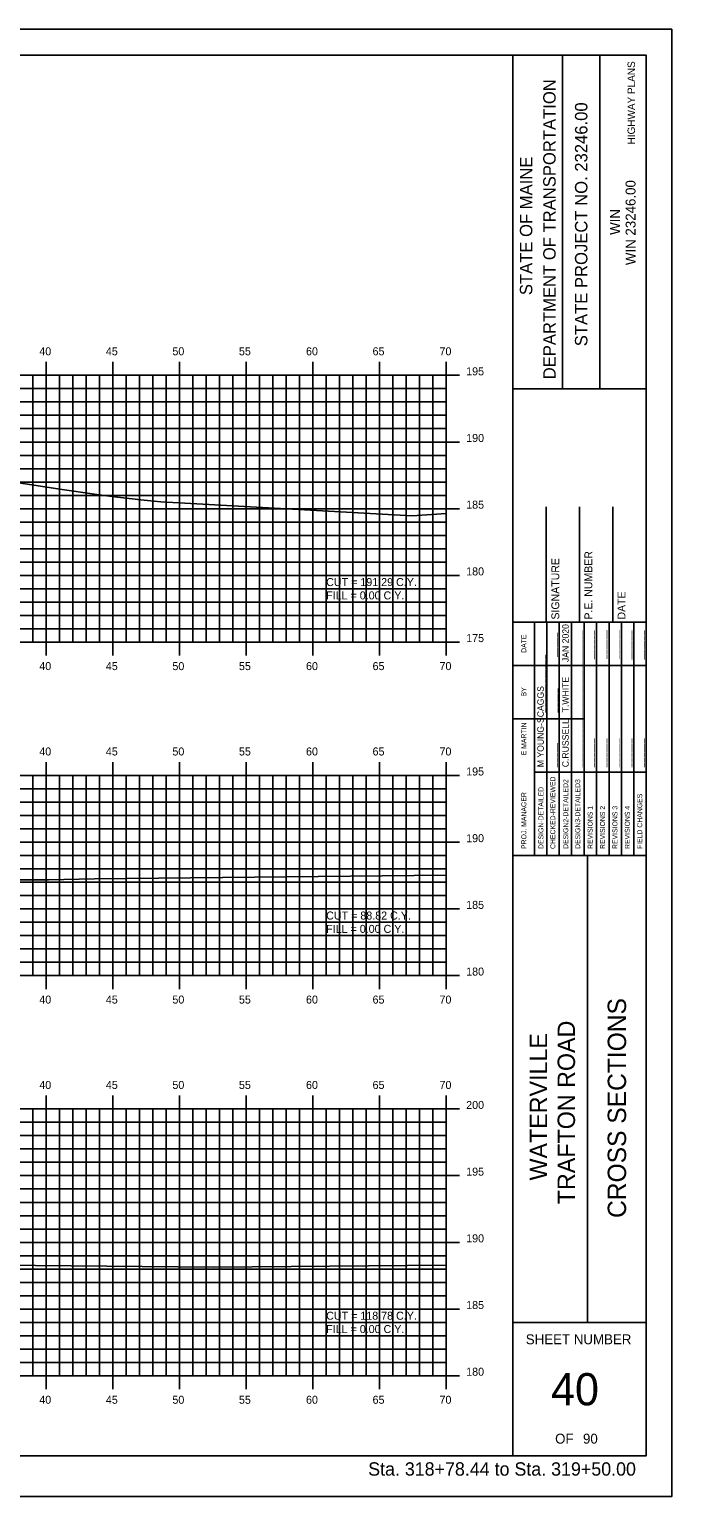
# Model space of a CAD drawing. Extents: x 1139428 to 1139598, y 608981 to 609091.
# Drawn here: x 1139550.2 to 1139598.4, y 608981.3 to 609091.3 of the extents above; entities that cross this region are included whole.
import ezdxf

# ---------------------------------------------------------------- set-up
doc = ezdxf.new("R2010")
doc.units = 0
for name, color, linetype in [('BORDER', 7, 'Continuous'), ('D_Text_Standard', 7, 'Continuous'), ('H_V ANNOTATION', 7, 'Continuous'), ('HIGHWAY_TITLE', 7, 'Continuous'), ('MAJOR', 7, 'Continuous'), ('MINOR', 7, 'Continuous'), ('PLOT BOUNDARY', 7, 'Continuous'), ('S_Roadway_Centerline', 7, 'Continuous')]:
    doc.layers.add(name, color=color, linetype=linetype)

msp = doc.modelspace()

# ---------------------------------------------------------------- linework, layer by layer
at = {"layer": 'BORDER'}
for p, q in [((1139586.46, 608984.34), (1139586.46, 609089.34)), ((1139590.19, 609064.33), (1139590.19, 609089.33)), ((1139592.99, 609064.33), (1139592.99, 609089.33)), ((1139586.46, 609064.33), (1139596.46, 609064.33)), ((1139588.96, 609046.84), (1139588.96, 609055.49)), ((1139591.46, 609046.84), (1139591.46, 609055.49)), ((1139593.96, 609046.84), (1139593.96, 609055.49)), ((1139586.46, 609046.84), (1139596.46, 609046.84)), ((1139586.46, 609029.34), (1139596.46, 609029.34)), ((1139592.05, 608994.34), (1139592.05, 609029.34)), ((1139586.46, 608994.34), (1139596.46, 608994.34))]:
    msp.add_line(p, q, dxfattribs=at)
msp.add_lwpolyline([(1139436.46, 608984.34), (1139596.46, 608984.34), (1139596.46, 609089.34), (1139436.46, 609089.34)], close=True, dxfattribs=at)
for points in [[(1139588.08, 609043.59), (1139588.08, 609046.84)], [(1139588.08, 609029.34), (1139588.08, 609046.13)], [(1139589.01, 609029.34), (1139589.01, 609046.84)], [(1139589.94, 609046.84), (1139589.94, 609029.34)], [(1139590.87, 609029.34), (1139590.87, 609046.84)], [(1139591.8, 609029.34), (1139591.8, 609046.84)], [(1139592.74, 609029.34), (1139592.74, 609046.84)], [(1139593.67, 609029.34), (1139593.67, 609046.84)], [(1139594.6, 609029.34), (1139594.6, 609046.84)], [(1139595.53, 609029.34), (1139595.53, 609046.84)], [(1139586.46, 609043.59), (1139596.46, 609043.59)], [(1139586.46, 609039.59), (1139588.08, 609039.59)], [(1139588.08, 609039.59), (1139591.8, 609039.59)], [(1139588.08, 609035.59), (1139596.46, 609035.59)]]:
    msp.add_lwpolyline(points, dxfattribs=at)
at = {"layer": 'MAJOR'}
for p, q in [((1139551.46, 609066.34), (1139551.46, 609065.34)), ((1139556.46, 609066.34), (1139556.46, 609065.34)), ((1139561.46, 609066.34), (1139561.46, 609065.34)), ((1139566.46, 609066.34), (1139566.46, 609065.34)), ((1139571.46, 609066.34), (1139571.46, 609065.34)), ((1139576.46, 609066.34), (1139576.46, 609065.34)), ((1139581.46, 609066.34), (1139581.46, 609065.34)), ((1139441.46, 609065.34), (1139581.46, 609065.34)), ((1139441.46, 609065.34), (1139581.46, 609065.34)), ((1139551.46, 609045.34), (1139551.46, 609065.34)), ((1139556.46, 609045.34), (1139556.46, 609065.34)), ((1139561.46, 609045.34), (1139561.46, 609065.34)), ((1139566.46, 609045.34), (1139566.46, 609065.34)), ((1139571.46, 609045.34), (1139571.46, 609065.34)), ((1139576.46, 609045.34), (1139576.46, 609065.34)), ((1139582.46, 609065.34), (1139580.46, 609065.34)), ((1139581.46, 609045.34), (1139581.46, 609065.34)), ((1139581.46, 609045.34), (1139581.46, 609065.34)), ((1139441.46, 609060.34), (1139581.46, 609060.34)), ((1139582.46, 609060.34), (1139580.46, 609060.34)), ((1139441.46, 609055.34), (1139581.46, 609055.34)), ((1139582.46, 609055.34), (1139580.46, 609055.34)), ((1139441.46, 609050.34), (1139581.46, 609050.34)), ((1139582.46, 609050.34), (1139580.46, 609050.34)), ((1139441.46, 609045.34), (1139581.46, 609045.34)), ((1139441.46, 609045.34), (1139581.46, 609045.34)), ((1139551.46, 609044.33), (1139551.46, 609045.34)), ((1139556.46, 609044.33), (1139556.46, 609045.34)), ((1139561.46, 609044.33), (1139561.46, 609045.34)), ((1139566.46, 609044.33), (1139566.46, 609045.34)), ((1139571.46, 609044.33), (1139571.46, 609045.34)), ((1139576.46, 609044.33), (1139576.46, 609045.34)), ((1139582.46, 609045.34), (1139580.46, 609045.34)), ((1139581.46, 609044.33), (1139581.46, 609045.34)), ((1139551.46, 609036.34), (1139551.46, 609035.34)), ((1139556.46, 609036.34), (1139556.46, 609035.34)), ((1139561.46, 609036.34), (1139561.46, 609035.34)), ((1139566.46, 609036.34), (1139566.46, 609035.34)), ((1139571.46, 609036.34), (1139571.46, 609035.34)), ((1139576.46, 609036.34), (1139576.46, 609035.34)), ((1139581.46, 609036.34), (1139581.46, 609035.34)), ((1139441.46, 609035.34), (1139581.46, 609035.34)), ((1139441.46, 609035.34), (1139581.46, 609035.34)), ((1139551.46, 609020.34), (1139551.46, 609035.34)), ((1139556.46, 609020.34), (1139556.46, 609035.34)), ((1139561.46, 609020.34), (1139561.46, 609035.34)), ((1139566.46, 609020.34), (1139566.46, 609035.34)), ((1139571.46, 609020.34), (1139571.46, 609035.34)), ((1139576.46, 609020.34), (1139576.46, 609035.34)), ((1139582.46, 609035.34), (1139580.46, 609035.34)), ((1139581.46, 609020.34), (1139581.46, 609035.34)), ((1139581.46, 609020.34), (1139581.46, 609035.34)), ((1139441.46, 609030.34), (1139581.46, 609030.34)), ((1139582.46, 609030.34), (1139580.46, 609030.34)), ((1139441.46, 609025.34), (1139581.46, 609025.34)), ((1139582.46, 609025.34), (1139580.46, 609025.34)), ((1139441.46, 609020.34), (1139581.46, 609020.34)), ((1139441.46, 609020.34), (1139581.46, 609020.34)), ((1139551.46, 609019.33), (1139551.46, 609020.34)), ((1139556.46, 609019.33), (1139556.46, 609020.34)), ((1139561.46, 609019.33), (1139561.46, 609020.34)), ((1139566.46, 609019.33), (1139566.46, 609020.34)), ((1139571.46, 609019.33), (1139571.46, 609020.34)), ((1139576.46, 609019.33), (1139576.46, 609020.34)), ((1139582.46, 609020.34), (1139580.46, 609020.34)), ((1139581.46, 609019.33), (1139581.46, 609020.34)), ((1139551.46, 609011.34), (1139551.46, 609010.34)), ((1139556.46, 609011.34), (1139556.46, 609010.34)), ((1139561.46, 609011.34), (1139561.46, 609010.34)), ((1139566.46, 609011.34), (1139566.46, 609010.34)), ((1139571.46, 609011.34), (1139571.46, 609010.34)), ((1139576.46, 609011.34), (1139576.46, 609010.34)), ((1139581.46, 609011.34), (1139581.46, 609010.34)), ((1139441.46, 609010.34), (1139581.46, 609010.34)), ((1139441.46, 609010.34), (1139581.46, 609010.34)), ((1139551.46, 608990.34), (1139551.46, 609010.34)), ((1139556.46, 608990.34), (1139556.46, 609010.34)), ((1139561.46, 608990.34), (1139561.46, 609010.34)), ((1139566.46, 608990.34), (1139566.46, 609010.34)), ((1139571.46, 608990.34), (1139571.46, 609010.34)), ((1139576.46, 608990.34), (1139576.46, 609010.34)), ((1139582.46, 609010.34), (1139580.46, 609010.34)), ((1139581.46, 608990.34), (1139581.46, 609010.34)), ((1139581.46, 608990.34), (1139581.46, 609010.34)), ((1139441.46, 609005.34), (1139581.46, 609005.34)), ((1139582.46, 609005.34), (1139580.46, 609005.34)), ((1139441.46, 609000.34), (1139581.46, 609000.34)), ((1139582.46, 609000.34), (1139580.46, 609000.34)), ((1139441.46, 608995.34), (1139581.46, 608995.34)), ((1139582.46, 608995.34), (1139580.46, 608995.34)), ((1139441.46, 608990.34), (1139581.46, 608990.34)), ((1139441.46, 608990.34), (1139581.46, 608990.34)), ((1139551.46, 608989.33), (1139551.46, 608990.34)), ((1139556.46, 608989.33), (1139556.46, 608990.34)), ((1139561.46, 608989.33), (1139561.46, 608990.34)), ((1139566.46, 608989.33), (1139566.46, 608990.34)), ((1139571.46, 608989.33), (1139571.46, 608990.34)), ((1139576.46, 608989.33), (1139576.46, 608990.34)), ((1139582.46, 608990.34), (1139580.46, 608990.34)), ((1139581.46, 608989.33), (1139581.46, 608990.34))]:
    msp.add_line(p, q, dxfattribs=at)
at = {"layer": 'MINOR'}
for p, q in [((1139550.46, 609045.34), (1139550.46, 609065.34)), ((1139552.46, 609045.34), (1139552.46, 609065.34)), ((1139553.46, 609045.34), (1139553.46, 609065.34)), ((1139554.46, 609045.34), (1139554.46, 609065.34)), ((1139555.46, 609045.34), (1139555.46, 609065.34)), ((1139557.46, 609045.34), (1139557.46, 609065.34)), ((1139558.46, 609045.34), (1139558.46, 609065.34)), ((1139559.46, 609045.34), (1139559.46, 609065.34)), ((1139560.46, 609045.34), (1139560.46, 609065.34)), ((1139562.46, 609045.34), (1139562.46, 609065.34)), ((1139563.46, 609045.34), (1139563.46, 609065.34)), ((1139564.46, 609045.34), (1139564.46, 609065.34)), ((1139565.46, 609045.34), (1139565.46, 609065.34)), ((1139567.46, 609045.34), (1139567.46, 609065.34)), ((1139568.46, 609045.34), (1139568.46, 609065.34)), ((1139569.46, 609045.34), (1139569.46, 609065.34)), ((1139570.46, 609045.34), (1139570.46, 609065.34)), ((1139572.46, 609045.34), (1139572.46, 609065.34)), ((1139573.46, 609045.34), (1139573.46, 609065.34)), ((1139574.46, 609045.34), (1139574.46, 609065.34)), ((1139575.46, 609045.34), (1139575.46, 609065.34)), ((1139577.46, 609045.34), (1139577.46, 609065.34)), ((1139578.46, 609045.34), (1139578.46, 609065.34)), ((1139579.46, 609045.34), (1139579.46, 609065.34)), ((1139580.46, 609045.34), (1139580.46, 609065.34)), ((1139441.46, 609064.34), (1139581.46, 609064.34)), ((1139581.46, 609064.34), (1139580.46, 609064.34)), ((1139441.46, 609063.34), (1139581.46, 609063.34)), ((1139441.46, 609062.34), (1139581.46, 609062.34)), ((1139581.46, 609063.34), (1139580.46, 609063.34)), ((1139581.46, 609062.34), (1139580.46, 609062.34)), ((1139441.46, 609061.34), (1139581.46, 609061.34)), ((1139581.46, 609061.34), (1139580.46, 609061.34)), ((1139441.46, 609059.34), (1139581.46, 609059.34)), ((1139581.46, 609059.34), (1139580.46, 609059.34)), ((1139441.46, 609058.34), (1139581.46, 609058.34)), ((1139581.46, 609058.34), (1139580.46, 609058.34)), ((1139441.46, 609057.34), (1139581.46, 609057.34)), ((1139581.46, 609057.34), (1139580.46, 609057.34)), ((1139441.46, 609056.34), (1139581.46, 609056.34)), ((1139581.46, 609056.34), (1139580.46, 609056.34)), ((1139441.46, 609054.34), (1139581.46, 609054.34)), ((1139581.46, 609054.34), (1139580.46, 609054.34)), ((1139441.46, 609053.34), (1139581.46, 609053.34)), ((1139581.46, 609053.34), (1139580.46, 609053.34)), ((1139441.46, 609052.34), (1139581.46, 609052.34)), ((1139441.46, 609051.34), (1139581.46, 609051.34)), ((1139581.46, 609052.34), (1139580.46, 609052.34)), ((1139581.46, 609051.34), (1139580.46, 609051.34)), ((1139441.46, 609049.34), (1139581.46, 609049.34)), ((1139581.46, 609049.34), (1139580.46, 609049.34)), ((1139441.46, 609048.34), (1139581.46, 609048.34)), ((1139581.46, 609048.34), (1139580.46, 609048.34)), ((1139441.46, 609047.34), (1139581.46, 609047.34)), ((1139581.46, 609047.34), (1139580.46, 609047.34)), ((1139441.46, 609046.34), (1139581.46, 609046.34)), ((1139581.46, 609046.34), (1139580.46, 609046.34)), ((1139550.46, 609020.34), (1139550.46, 609035.34)), ((1139552.46, 609020.34), (1139552.46, 609035.34)), ((1139553.46, 609020.34), (1139553.46, 609035.34)), ((1139554.46, 609020.34), (1139554.46, 609035.34)), ((1139555.46, 609020.34), (1139555.46, 609035.34)), ((1139557.46, 609020.34), (1139557.46, 609035.34)), ((1139558.46, 609020.34), (1139558.46, 609035.34)), ((1139559.46, 609020.34), (1139559.46, 609035.34)), ((1139560.46, 609020.34), (1139560.46, 609035.34)), ((1139562.46, 609020.34), (1139562.46, 609035.34)), ((1139563.46, 609020.34), (1139563.46, 609035.34)), ((1139564.46, 609020.34), (1139564.46, 609035.34)), ((1139565.46, 609020.34), (1139565.46, 609035.34)), ((1139567.46, 609020.34), (1139567.46, 609035.34)), ((1139568.46, 609020.34), (1139568.46, 609035.34)), ((1139569.46, 609020.34), (1139569.46, 609035.34)), ((1139570.46, 609020.34), (1139570.46, 609035.34)), ((1139572.46, 609020.34), (1139572.46, 609035.34)), ((1139573.46, 609020.34), (1139573.46, 609035.34)), ((1139574.46, 609020.34), (1139574.46, 609035.34)), ((1139575.46, 609020.34), (1139575.46, 609035.34)), ((1139577.46, 609020.34), (1139577.46, 609035.34)), ((1139578.46, 609020.34), (1139578.46, 609035.34)), ((1139579.46, 609020.34), (1139579.46, 609035.34)), ((1139580.46, 609020.34), (1139580.46, 609035.34)), ((1139441.46, 609034.34), (1139581.46, 609034.34)), ((1139581.46, 609034.34), (1139580.46, 609034.34)), ((1139441.46, 609033.34), (1139581.46, 609033.34)), ((1139581.46, 609033.34), (1139580.46, 609033.34)), ((1139441.46, 609032.34), (1139581.46, 609032.34)), ((1139581.46, 609032.34), (1139580.46, 609032.34)), ((1139441.46, 609031.34), (1139581.46, 609031.34)), ((1139581.46, 609031.34), (1139580.46, 609031.34)), ((1139441.46, 609029.34), (1139581.46, 609029.34)), ((1139581.46, 609029.34), (1139580.46, 609029.34)), ((1139441.46, 609028.34), (1139581.46, 609028.34)), ((1139581.46, 609028.34), (1139580.46, 609028.34)), ((1139441.46, 609027.34), (1139581.46, 609027.34)), ((1139581.46, 609027.34), (1139580.46, 609027.34)), ((1139441.46, 609026.34), (1139581.46, 609026.34)), ((1139581.46, 609026.34), (1139580.46, 609026.34)), ((1139441.46, 609024.34), (1139581.46, 609024.34)), ((1139581.46, 609024.34), (1139580.46, 609024.34)), ((1139441.46, 609023.34), (1139581.46, 609023.34)), ((1139581.46, 609023.34), (1139580.46, 609023.34)), ((1139441.46, 609022.34), (1139581.46, 609022.34)), ((1139581.46, 609022.34), (1139580.46, 609022.34)), ((1139441.46, 609021.34), (1139581.46, 609021.34)), ((1139581.46, 609021.34), (1139580.46, 609021.34)), ((1139550.46, 608990.34), (1139550.46, 609010.34)), ((1139552.46, 608990.34), (1139552.46, 609010.34)), ((1139553.46, 608990.34), (1139553.46, 609010.34)), ((1139554.46, 608990.34), (1139554.46, 609010.34)), ((1139555.46, 608990.34), (1139555.46, 609010.34)), ((1139557.46, 608990.34), (1139557.46, 609010.34)), ((1139558.46, 608990.34), (1139558.46, 609010.34)), ((1139559.46, 608990.34), (1139559.46, 609010.34)), ((1139560.46, 608990.34), (1139560.46, 609010.34)), ((1139562.46, 608990.34), (1139562.46, 609010.34)), ((1139563.46, 608990.34), (1139563.46, 609010.34)), ((1139564.46, 608990.34), (1139564.46, 609010.34)), ((1139565.46, 608990.34), (1139565.46, 609010.34)), ((1139567.46, 608990.34), (1139567.46, 609010.34)), ((1139568.46, 608990.34), (1139568.46, 609010.34)), ((1139569.46, 608990.34), (1139569.46, 609010.34)), ((1139570.46, 608990.34), (1139570.46, 609010.34)), ((1139572.46, 608990.34), (1139572.46, 609010.34)), ((1139573.46, 608990.34), (1139573.46, 609010.34)), ((1139574.46, 608990.34), (1139574.46, 609010.34)), ((1139575.46, 608990.34), (1139575.46, 609010.34)), ((1139577.46, 608990.34), (1139577.46, 609010.34)), ((1139578.46, 608990.34), (1139578.46, 609010.34)), ((1139579.46, 608990.34), (1139579.46, 609010.34)), ((1139580.46, 608990.34), (1139580.46, 609010.34)), ((1139441.46, 609009.34), (1139581.46, 609009.34)), ((1139581.46, 609009.34), (1139580.46, 609009.34)), ((1139441.46, 609008.34), (1139581.46, 609008.34)), ((1139441.46, 609007.34), (1139581.46, 609007.34)), ((1139581.46, 609008.34), (1139580.46, 609008.34)), ((1139581.46, 609007.34), (1139580.46, 609007.34)), ((1139441.46, 609006.34), (1139581.46, 609006.34)), ((1139581.46, 609006.34), (1139580.46, 609006.34)), ((1139441.46, 609004.34), (1139581.46, 609004.34)), ((1139581.46, 609004.34), (1139580.46, 609004.34)), ((1139441.46, 609003.34), (1139581.46, 609003.34)), ((1139581.46, 609003.34), (1139580.46, 609003.34)), ((1139441.46, 609002.34), (1139581.46, 609002.34)), ((1139581.46, 609002.34), (1139580.46, 609002.34)), ((1139441.46, 609001.34), (1139581.46, 609001.34)), ((1139581.46, 609001.34), (1139580.46, 609001.34)), ((1139441.46, 608999.34), (1139581.46, 608999.34)), ((1139581.46, 608999.34), (1139580.46, 608999.34)), ((1139441.46, 608998.34), (1139581.46, 608998.34)), ((1139581.46, 608998.34), (1139580.46, 608998.34)), ((1139441.46, 608997.34), (1139581.46, 608997.34)), ((1139441.46, 608996.34), (1139581.46, 608996.34)), ((1139581.46, 608997.34), (1139580.46, 608997.34)), ((1139581.46, 608996.34), (1139580.46, 608996.34)), ((1139441.46, 608994.34), (1139581.46, 608994.34)), ((1139581.46, 608994.34), (1139580.46, 608994.34)), ((1139441.46, 608993.34), (1139581.46, 608993.34)), ((1139581.46, 608993.34), (1139580.46, 608993.34)), ((1139441.46, 608992.34), (1139581.46, 608992.34)), ((1139581.46, 608992.34), (1139580.46, 608992.34)), ((1139441.46, 608991.34), (1139581.46, 608991.34)), ((1139581.46, 608991.34), (1139580.46, 608991.34))]:
    msp.add_line(p, q, dxfattribs=at)
at = {"layer": 'PLOT BOUNDARY'}
msp.add_lwpolyline([(1139428.37, 608981.28), (1139598.37, 608981.28), (1139598.37, 609091.28), (1139428.37, 609091.28)], close=True, dxfattribs=at)
at = {"layer": 'S_Roadway_Centerline'}
for points in [[(1139547.1, 609057.63), (1139552.67, 609056.77), (1139555.09, 609056.43), (1139556.4, 609056.26), (1139558.57, 609056), (1139560.05, 609055.85), (1139578.9, 609054.81), (1139581.46, 609054.98)], [(1139549.02, 609027.51), (1139551.64, 609027.51), (1139555.1, 609027.59), (1139581.46, 609027.86)], [(1139480.5, 609001.04), (1139487.2, 609000.88), (1139493.23, 609000.68), (1139497.03, 609000.64), (1139498.49, 609000.7), (1139503.92, 609000.85), (1139505.94, 609000.86), (1139514.15, 609000.91), (1139514.22, 609000.88), (1139525.32, 609000.67), (1139525.72, 609000.67), (1139526.35, 609000.53), (1139530.63, 608999.64), (1139534.75, 608998.92), (1139536.79, 608998.82), (1139539.97, 608998.7), (1139564.01, 608998.47), (1139581.46, 608998.62)]]:
    msp.add_lwpolyline(points, dxfattribs=at)

# ---------------------------------------------------------------- texts
at = {"layer": 'BORDER'}
for s, height, p in [('DEPARTMENT OF TRANSPORTATION', 0.9318, (1139589.67, 609065.04)), ('STATE PROJECT NO. 23246.00', 0.9318, (1139592.05, 609067.52)), ('STATE OF MAINE', 0.9318, (1139587.92, 609071.35)), ('WIN 23246.00', 0.7453, (1139595.66, 609073.6)), ('WIN', 0.745, (1139594.5, 609075.87)), ('SIGNATURE', 0.591, (1139589.94, 609047.03)), ('P.E. NUMBER', 0.5906, (1139592.42, 609047.03)), ('DATE', 0.591, (1139594.9, 609047.03)), ('DATE', 0.371, (1139587.47, 609044.54)), ('_____', 0.485, (1139589.68, 609044.24)), ('JAN 2020', 0.485, (1139590.65, 609043.84)), ('______', 0.485, (1139591.54, 609044.06)), ('______', 0.485, (1139592.47, 609044.06)), ('______', 0.485, (1139593.41, 609044.07)), ('______', 0.485, (1139594.34, 609044.07)), ('______', 0.485, (1139595.27, 609044.04)), ('______', 0.485, (1139596.2, 609044.04)), ('____________', 0.4845, (1139588.78, 609040.07)), ('____________', 0.4845, (1139591.54, 609040.07)), ('T.WHITE', 0.485, (1139590.65, 609040.07)), ('BY', 0.371, (1139587.47, 609041.27)), ('M YOUNG-SCAGGS', 0.4845, (1139588.78, 609035.96)), ('_____', 0.485, (1139589.72, 609040.07)), ('C.RUSSELL', 0.485, (1139590.65, 609035.96)), ('____________', 0.4845, (1139591.54, 609035.96)), ('E MARTIN', 0.373, (1139587.47, 609036.85)), ('______', 0.485, (1139592.47, 609035.96)), ('______', 0.485, (1139593.41, 609035.96)), ('______', 0.485, (1139594.34, 609035.96)), ('______', 0.485, (1139595.27, 609035.96)), ('______', 0.485, (1139596.2, 609035.96)), ('_____', 0.485, (1139589.68, 609035.96)), ('CHECKED-REVIEWED', 0.3727, (1139589.64, 609029.83)), ('DESIGN2-DETAILED2', 0.3727, (1139590.61, 609029.83)), ('DESIGN3-DETAILED3', 0.3727, (1139591.51, 609029.83)), ('PROJ. MANAGER', 0.3727, (1139587.47, 609029.83)), ('DESIGN-DETAILED', 0.3727, (1139588.75, 609029.83)), ('FIELD CHANGES', 0.3727, (1139596.16, 609029.83)), ('REVISIONS 1', 0.3727, (1139592.44, 609029.83)), ('REVISIONS 2', 0.3727, (1139593.37, 609029.83)), ('REVISIONS 3', 0.3727, (1139594.3, 609029.83)), ('REVISIONS 4', 0.3727, (1139595.23, 609029.83)), ('CROSS SECTIONS', 1.3779, (1139594.95, 609002.17))]:
    msp.add_text(s, height=height, rotation=90, dxfattribs=at).set_placement(p)
for s, height, p in [('SHEET NUMBER', 0.7453, (1139587.43, 608992.7)), ('40', 2.419, (1139589.32, 608988.12)), ('OF', 0.745, (1139589.63, 608985.25)), ('90', 0.745, (1139591.72, 608985.25))]:
    msp.add_text(s, height=height, dxfattribs=at).set_placement(p)
at = {"layer": 'D_Text_Standard'}
for s, p in [('CUT = 191.29 C.Y.', (1139572.46, 609049.54)), ('FILL = 0.00 C.Y.', (1139572.46, 609048.54)), ('CUT = 88.82 C.Y.', (1139572.46, 609024.54)), ('FILL = 0.00 C.Y.', (1139572.46, 609023.54)), ('CUT = 118.78 C.Y.', (1139572.46, 608994.54)), ('FILL = 0.00 C.Y.', (1139572.46, 608993.54))]:
    msp.add_text(s, height=0.6, dxfattribs=at).set_placement(p)
at = {"layer": 'H_V ANNOTATION'}
for s, height, p in [('40', 0.6, (1139550.95, 609066.84)), ('45', 0.6, (1139555.94, 609066.84)), ('50', 0.6, (1139560.93, 609066.84)), ('55', 0.6, (1139565.92, 609066.84)), ('60', 0.6, (1139570.95, 609066.84)), ('65', 0.6, (1139575.94, 609066.84)), ('70', 0.6, (1139580.96, 609066.84)), ('195', 0.6, (1139582.96, 609065.34)), ('190', 0.6, (1139582.96, 609060.34)), ('185', 0.6, (1139582.96, 609055.34)), ('180', 0.6, (1139582.96, 609050.34)), ('175', 0.6, (1139582.96, 609045.34)), ('40', 0.6, (1139550.95, 609043.24)), ('45', 0.6, (1139555.94, 609043.24)), ('50', 0.6, (1139560.93, 609043.24)), ('55', 0.6, (1139565.92, 609043.24)), ('60', 0.6, (1139570.95, 609043.24)), ('65', 0.6, (1139575.94, 609043.24)), ('70', 0.6, (1139580.96, 609043.24)), ('40', 0.6, (1139550.95, 609036.84)), ('45', 0.6, (1139555.94, 609036.84)), ('50', 0.6, (1139560.93, 609036.84)), ('55', 0.6, (1139565.92, 609036.84)), ('60', 0.6, (1139570.95, 609036.84)), ('65', 0.6, (1139575.94, 609036.84)), ('70', 0.6, (1139580.96, 609036.84)), ('195', 0.6, (1139582.96, 609035.34)), ('190', 0.6, (1139582.96, 609030.34)), ('185', 0.6, (1139582.96, 609025.34)), ('180', 0.6, (1139582.96, 609020.34)), ('40', 0.6, (1139550.95, 609018.24)), ('45', 0.6, (1139555.94, 609018.24)), ('50', 0.6, (1139560.93, 609018.24)), ('55', 0.6, (1139565.92, 609018.24)), ('60', 0.6, (1139570.95, 609018.24)), ('65', 0.6, (1139575.94, 609018.24)), ('70', 0.6, (1139580.96, 609018.24)), ('40', 0.6, (1139550.95, 609011.84)), ('45', 0.6, (1139555.94, 609011.84)), ('50', 0.6, (1139560.93, 609011.84)), ('55', 0.6, (1139565.92, 609011.84)), ('60', 0.6, (1139570.95, 609011.84)), ('65', 0.6, (1139575.94, 609011.84)), ('70', 0.6, (1139580.96, 609011.84)), ('200', 0.6, (1139582.96, 609010.34)), ('195', 0.6, (1139582.96, 609005.34)), ('190', 0.6, (1139582.96, 609000.34)), ('185', 0.6, (1139582.96, 608995.34)), ('180', 0.6, (1139582.96, 608990.34)), ('40', 0.6, (1139550.95, 608988.24)), ('45', 0.6, (1139555.94, 608988.24)), ('50', 0.6, (1139560.93, 608988.24)), ('55', 0.6, (1139565.92, 608988.24)), ('60', 0.6, (1139570.95, 608988.24)), ('65', 0.6, (1139575.94, 608988.24)), ('70', 0.6, (1139580.96, 608988.24)), ('Sta. 318+78.44 to Sta. 319+50.00', 1.0002, (1139575.61, 608982.85))]:
    msp.add_text(s, height=height, dxfattribs=at).set_placement(p)
at = {"layer": 'HIGHWAY_TITLE'}
for s, height, p in [('HIGHWAY PLANS', 0.559, (1139595.62, 609082.65)), ('TRAFTON ROAD', 1.3043, (1139591.12, 609003.2)), ('WATERVILLE', 1.304, (1139589.03, 609004.98))]:
    msp.add_text(s, height=height, rotation=90, dxfattribs=at).set_placement(p)

doc.saveas('drawing.dxf')
